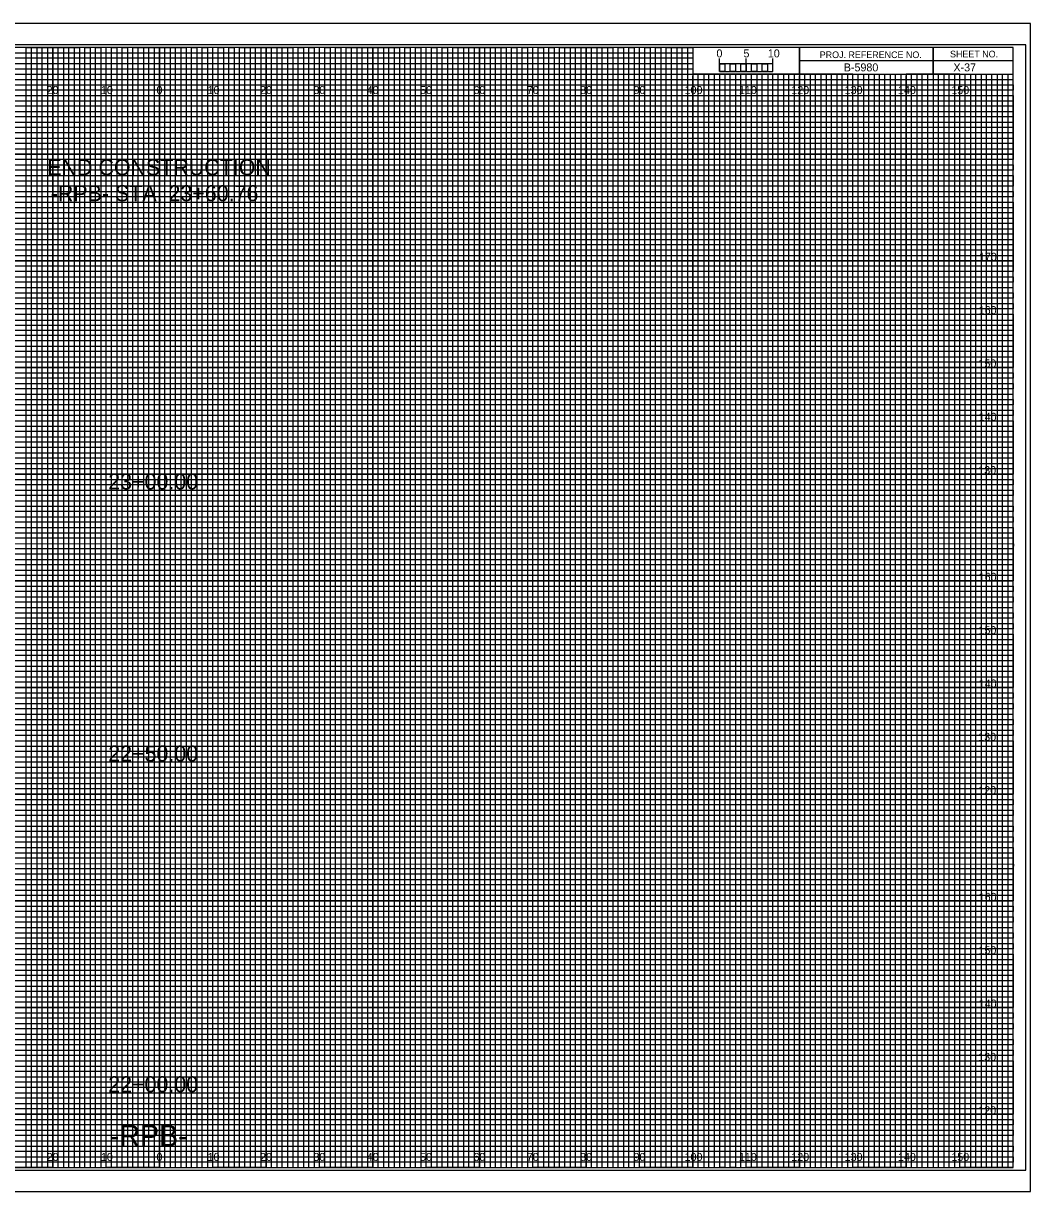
# Model space of a CAD drawing. Extents: x -13 to 323, y -5 to 1094.
# Drawn here: x 134.5 to 323.3, y 875.5 to 1094.5 of the extents above; entities that cross this region are included whole.
import ezdxf

# ---------------------------------------------------------------- set-up
doc = ezdxf.new("R2010")
doc.units = 0
for name, color, linetype in [('Exist Cross Section Cell', 7, 'Continuous'), ('Exist XS Center Line Elevation Label', 7, 'Continuous'), ('Exist XS Ground Line', 7, 'Continuous'), ('Prop CMT Concrete Structures', 7, 'Continuous'), ('Prop CMT Guardrail Graphics', 7, 'Continuous'), ('Prop CMT Pvmt Course 1', 7, 'Continuous'), ('Prop CMT Pvmt Course 1 CG', 7, 'Continuous'), ('Prop CMT Pvmt Course 2', 7, 'Continuous'), ('Prop CMT Pvmt Course 3', 7, 'Continuous'), ('Prop CMT Pvmt Surface', 7, 'Continuous'), ('Prop CMT Pvmt Surface Shoulder', 7, 'Continuous'), ('Prop CMT Shld Paved Course 1', 7, 'Continuous'), ('Prop CMT Shld Paved Course 2', 7, 'Continuous'), ('Prop CMT Shld Paved Course 3', 7, 'Continuous'), ('Prop CMT Slope Grass', 7, 'Continuous'), ('Prop CMT Subgrade Earthwork', 7, 'Continuous'), ('Scratch_Level_1', 7, 'Continuous')]:
    doc.layers.add(name, color=color, linetype=linetype)

msp = doc.modelspace()

# ---------------------------------------------------------------- linework, layer by layer
at = {"layer": 'Exist XS Center Line Elevation Label'}
for points in [[(125, 880), (135, 880), (135, 1090), (145, 1090), (145, 880), (155, 880), (155, 1090), (165, 1090), (165, 880), (175, 880), (175, 1090), (185, 1090), (185, 880), (195, 880), (195, 1090), (205, 1090), (205, 880), (215, 880), (215, 1090), (225, 1090), (225, 880), (235, 880), (235, 1090), (245, 1090), (245, 880), (255, 880), (255, 1090), (259.93, 1090), (260, 1090), (260, 1085), (264.99, 1085), (264.99, 880), (275, 880), (275, 1085), (285, 1085), (285, 880), (295, 880), (295, 1085), (305, 1085), (305, 880), (315, 880), (315, 1085)], [(0, 1085), (275, 1085)], [(0, 1065), (320, 1065), (320, 1075), (0, 1075)], [(0, 1045), (320, 1045), (320, 1055), (0, 1055)], [(0, 1025), (320, 1025), (320, 1035), (0, 1035)], [(0, 1005), (320, 1005), (320, 1015), (0, 1015)], [(0, 985), (320, 985), (320, 995), (0, 995)], [(0, 965), (320, 965), (320, 975), (0, 975)], [(0, 945), (320, 945), (320, 955), (0, 955)], [(0, 925), (320, 925), (320, 935), (0, 935)], [(0, 905), (320, 905), (320, 915), (0, 915)], [(0, 885), (320, 885), (320, 895), (0, 895)]]:
    msp.add_lwpolyline(points, dxfattribs=at)
at = {"layer": 'Exist XS Ground Line'}
for p, q in [((150, 1090), (140, 1090)), ((140, 1090), (140, 880)), ((150, 880), (150, 1090)), ((170, 1090), (160, 1090)), ((160, 1090), (160, 880)), ((170, 880), (170, 1090)), ((190, 1090), (180, 1090)), ((180, 1090), (180, 880)), ((190, 880), (190, 1090)), ((210, 1090), (200, 1090)), ((200, 1090), (200, 880)), ((210, 880), (210, 1090)), ((230, 1090), (220, 1090)), ((220, 1090), (220, 880)), ((230, 880), (230, 1090)), ((250, 1090), (240, 1090)), ((240, 1090), (240, 880)), ((250, 880), (250, 1090)), ((260, 1090), (260, 880)), ((270, 880), (270, 1085)), ((290, 1085), (280, 1085)), ((280, 1085), (280, 880)), ((290, 880), (290, 1085)), ((310, 1085), (300, 1085)), ((300, 1085), (300, 880)), ((310, 880), (310, 1085)), ((140, 880), (130, 880)), ((160, 880), (150, 880)), ((180, 880), (170, 880)), ((200, 880), (190, 880)), ((220, 880), (210, 880)), ((240, 880), (230, 880)), ((260, 880), (250, 880)), ((280, 880), (270, 880)), ((300, 880), (290, 880)), ((320, 880), (310, 880)), ((320, 880), (320, 880))]:
    msp.add_line(p, q, dxfattribs=at)
for points in [[(0, 1080), (320, 1080), (320, 1070), (0, 1070)], [(0, 1060), (320, 1060), (320, 1050), (0, 1050)], [(0, 1040), (320, 1040), (320, 1030), (0, 1030)], [(0, 1020), (320, 1020), (320, 1010), (0, 1010)], [(0, 1000), (320, 1000), (320, 990), (0, 990)], [(0, 980), (320, 980), (320, 970), (0, 970)], [(0, 960), (320, 960), (320, 950), (0, 950)], [(0, 940), (320, 940), (320, 930), (0, 930)], [(0, 920), (320, 920), (320, 910), (0, 910)], [(0, 900), (320, 900), (320, 890), (0, 890)]]:
    msp.add_lwpolyline(points, dxfattribs=at)
at = {"layer": 'Prop CMT Pvmt Course 2'}
for p, q in [((265, 1085.49), (265, 1087.9)), ((265, 1086.9), (265, 1087.9)), ((270, 1085.49), (270, 1087.9)), ((275, 1085.49), (275, 1087.9)), ((275, 1086.9), (275, 1087.9))]:
    msp.add_line(p, q, dxfattribs=at)
for points in [[(275, 1086.9), (265, 1086.9), (265, 1085.49), (275, 1085.49)], [(265, 1086.9), (266, 1086.9), (266, 1085.49), (265, 1085.49)], [(267, 1086.9), (268, 1086.9), (268, 1085.49), (267, 1085.49)], [(269, 1086.9), (270, 1086.9), (270, 1085.49), (269, 1085.49)], [(271, 1086.9), (272, 1086.9), (272, 1085.49), (271, 1085.49)], [(273, 1086.9), (274, 1086.9), (274, 1085.49), (273, 1085.49)]]:
    msp.add_lwpolyline(points, close=True, dxfattribs=at)
at = {"layer": 'Prop CMT Pvmt Course 3'}
msp.add_lwpolyline([(-13.4, 875.5), (323.3, 875.5), (323.3, 1094.5), (-13.4, 1094.5)], close=True, dxfattribs=at)
at = {"layer": 'Prop CMT Pvmt Surface'}
for p, q in [((140, 880), (140, 1090)), ((150, 880), (150, 1090)), ((160, 880), (160, 1090)), ((170, 880), (170, 1090)), ((180, 880), (180, 1090)), ((190, 880), (190, 1090)), ((200, 880), (200, 1090)), ((210, 880), (210, 1090)), ((220, 880), (220, 1090)), ((230, 880), (230, 1090)), ((240, 880), (240, 1090)), ((250, 880), (250, 1090)), ((260, 880), (260, 1084.69)), ((270, 880), (270, 1084.69)), ((280, 880), (280, 1084.69)), ((290, 880), (290, 1084.69)), ((300, 880), (300, 1084.69)), ((310, 880), (310, 1084.69)), ((0, 1080), (320, 1080)), ((0, 1070), (320, 1070)), ((0, 1060), (320, 1060)), ((0, 1050), (320, 1050)), ((0, 1040), (320, 1040)), ((0, 1030), (320, 1030)), ((0, 1020), (320, 1020)), ((0, 1010), (320, 1010)), ((0, 1000), (320, 1000)), ((0, 990), (320, 990)), ((0, 980), (320, 980)), ((0, 970), (320, 970)), ((0, 960), (320, 960)), ((0, 950), (320, 950)), ((0, 940), (320, 940)), ((0, 930), (320, 930)), ((0, 920), (320, 920)), ((0, 910), (320, 910)), ((0, 900), (320, 900)), ((0, 890), (320, 890))]:
    msp.add_line(p, q, dxfattribs=at)
at = {"layer": 'Prop CMT Pvmt Surface Shoulder'}
for p, q in [((323.3, 1094.5), (-13.4, 1094.5)), ((-13.4, 875.5), (323.3, 875.5))]:
    msp.add_line(p, q, dxfattribs=at)
at = {"layer": 'Prop CMT Shld Paved Course 1'}
for p, q in [((0, 1089), (260, 1089)), ((260, 1089), (260, 1087.98)), ((260, 1087.98), (0, 1087.98)), ((0, 1087), (260, 1087)), ((260, 1087), (260, 1085.89)), ((260, 1085.89), (0, 1085.89)), ((0, 1084), (320, 1084))]:
    msp.add_line(p, q, dxfattribs=at)
for points in [[(0, 1083), (270, 1083), (320, 1083), (320, 1082), (0, 1082)], [(0, 1081), (320, 1081), (320, 1079), (0, 1079)], [(0, 1078), (320, 1078), (320, 1077), (0, 1076.98)], [(0, 1076), (320, 1076), (320, 1074), (0, 1074)], [(0, 1073), (320, 1073), (320, 1072), (0, 1072)], [(0, 1071), (320, 1071), (320, 1069), (0, 1069)], [(0, 1068), (320, 1068), (320, 1067), (0, 1067)], [(0, 1066), (320, 1066), (320, 1064), (0, 1064)], [(0, 1063), (320, 1063), (320, 1062), (0, 1062)], [(0, 1061), (320, 1061), (320, 1059), (0, 1059)], [(0, 1058), (320, 1058), (320, 1057), (0, 1057)], [(0, 1056), (320, 1056), (320, 1053.95), (320, 1053), (320, 1052), (0, 1052)], [(0, 1054), (320, 1054), (320, 1053), (0, 1053)], [(0, 1051), (320, 1051), (320, 1049), (0, 1049.03)], [(0, 1049.03), (320, 1049), (320, 1048), (0, 1048)], [(0, 1047), (320, 1047), (320, 1046), (0, 1046)], [(0, 1044), (320, 1044), (320, 1043), (0, 1043)], [(0, 1042), (320, 1042), (320, 1041), (0, 1041)], [(-0.07, 1038.89), (320, 1038.89), (320, 1037.88), (-0.07, 1037.88)], [(0, 1037), (320, 1037), (320, 1036), (0, 1036)], [(0, 1034), (320, 1034), (320, 1033), (0, 1033)], [(0, 1032), (320, 1032), (320, 1031), (0, 1031)], [(0, 1029), (320, 1029), (320, 1028), (0, 1028)], [(0, 1027), (320, 1027), (320, 1026), (0, 1026)], [(0, 1024), (320, 1024), (320, 1023), (0, 1023)], [(0, 1022), (320, 1022), (320, 1021), (0, 1021)], [(0, 1019), (320, 1019), (319.99, 1017.98), (0, 1018)], [(0, 1017), (320, 1017), (320, 1016), (0, 1016)], [(0, 1014), (320, 1014), (320, 1013), (0, 1013)], [(0, 1012), (320, 1012), (320, 1011), (0, 1011)], [(0, 1009), (320, 1009), (320, 1008), (0, 1008)], [(0, 1007), (320, 1007), (320, 1006), (0, 1006)], [(0, 1004), (320, 1004), (320, 1003), (0, 1003)], [(0, 1002), (320, 1002), (320, 1001), (0, 1001)], [(0, 999), (320, 999), (320, 998), (0, 998)], [(0, 996.99), (320.07, 996.91), (320, 996), (0, 996)], [(0, 994), (320, 994), (320, 993), (0, 993)], [(0, 992), (320, 992), (320, 991), (0, 991)], [(0, 989), (320, 989), (320, 988), (0, 988)], [(0, 987), (320, 987), (320, 986), (0, 986)], [(0, 984), (320, 984), (320, 983), (0, 983)], [(0, 982), (320, 982), (320, 981), (0, 981)], [(0, 979), (320, 979), (320, 978), (0, 978)], [(0, 977), (320, 977), (320, 976), (0, 976)], [(0, 974), (320, 974), (320, 973), (0, 973)], [(0, 972), (320, 972), (320, 971), (0, 971)], [(0, 969), (320, 969), (320, 968), (0, 968)], [(0, 967), (320, 967), (320, 966), (0, 966)], [(0, 964), (320, 964), (320, 963), (0, 963)], [(0, 962), (320, 962), (320, 961), (0, 961)], [(0, 959), (320, 959), (319.99, 957.98), (0, 958)], [(0, 957), (320, 957), (320, 956), (0, 956)], [(0, 954), (320, 954), (320, 953), (0, 953)], [(0, 952), (320, 952), (320, 951), (0, 951)], [(0, 949), (320, 949), (320, 948), (0, 948)], [(0, 947), (320, 947), (320, 946), (0, 946)], [(0, 944), (320, 944), (320, 943), (0, 943)], [(0, 942), (320, 942), (320, 941), (0, 941)], [(0, 939), (320, 939), (320, 938), (0, 938)], [(0, 936.99), (320.07, 936.91), (320, 936), (0, 936)], [(0, 934), (320, 934), (320, 933), (0, 933)], [(0, 932), (320, 932), (320, 931), (0, 931)], [(0, 929), (320, 929), (320, 928), (0, 928)], [(0, 927), (320, 927), (320, 926), (0, 926)], [(0, 924), (320, 924), (320, 923), (0, 923)], [(0, 922), (320, 922), (320, 921), (0, 921)], [(0, 919), (320, 919), (320, 918), (0, 918)], [(0, 917), (320, 917), (320, 916), (0, 916)], [(0, 914), (320, 914), (320, 913), (0, 913)], [(0, 912), (320, 912), (320, 911), (0, 911)], [(0, 909), (320, 909), (320, 908), (0, 908)], [(0, 907), (320, 907), (320, 906), (0, 906)], [(0, 904), (320, 904), (320, 903), (0, 903)], [(0, 902), (320, 902), (320, 901), (0, 901)], [(0, 899), (320, 899), (320, 898), (0, 898)], [(0, 897), (320, 897), (320, 896), (0, 896)], [(0, 894), (320, 894), (320, 893), (0, 893)], [(0, 892), (320, 892), (320, 891), (0, 891)], [(0, 889), (320, 889), (320, 888), (0, 888)], [(0, 887), (320, 887), (320, 886), (0, 886)], [(0, 884), (320, 884), (320, 883), (0, 883)], [(0, 882), (320, 882), (320, 881), (0, 881)]]:
    msp.add_lwpolyline(points, dxfattribs=at)
at = {"layer": 'Prop CMT Shld Paved Course 2'}
for p, q in [((305, 1090), (305, 1085)), ((305, 1085), (305, 1090)), ((280, 1087.5), (280, 1085)), ((320, 1087.49), (280, 1087.49)), ((280, 1085), (320, 1085))]:
    msp.add_line(p, q, dxfattribs=at)
for points in [[(320, 1090), (0, 1090), (0, 880), (320, 880)], [(280, 1090), (260, 1090), (260, 1085.03), (280, 1085.03)], [(320, 1090), (280, 1090), (280, 1085), (320, 1085)]]:
    msp.add_lwpolyline(points, close=True, dxfattribs=at)
at = {"layer": 'Prop CMT Shld Paved Course 3'}
for p, q in [((267, 1085), (266.01, 1085)), ((266.01, 1085), (266.01, 880)), ((267, 880), (267, 1085)), ((269, 1085), (268, 1085)), ((268, 1085), (268, 880)), ((269, 880), (269, 1085)), ((266.01, 880), (265, 880)), ((268, 880), (267, 880))]:
    msp.add_line(p, q, dxfattribs=at)
for points in [[(135, 880), (136, 880), (136, 1090), (137, 1090), (137, 880)], [(137, 880), (138, 880), (138, 1090), (139, 1090), (139, 880)], [(140, 880), (141, 880), (141, 1090), (142, 1090), (142, 880)], [(142, 880), (143, 880), (143, 1090), (144, 1090), (144, 880)], [(145, 880), (146, 880), (146, 1090), (147, 1090), (147, 880)], [(147, 880), (148, 880), (148, 1090), (149, 1090), (149, 880)], [(150, 880), (151, 880), (151, 1090), (152, 1090), (152, 880)], [(152, 880), (153, 880), (153, 1090), (154, 1090), (154, 880)], [(155, 880), (156, 880), (156, 1090), (157, 1090), (157, 880)], [(157, 880), (158, 880), (158, 1090), (159, 1090), (159, 880)], [(160, 880), (161, 880), (161, 1090), (162, 1090), (162, 880)], [(162, 880), (163, 880), (163, 1090), (164, 1090), (164, 880)], [(165, 880), (166, 880), (166, 1090), (167, 1090), (167, 880)], [(167, 880), (168, 880), (168, 1090), (169, 1090), (169, 880)], [(170, 880), (171, 880), (171, 1090), (172, 1090), (172, 880)], [(172, 880), (173, 880), (173, 1090), (174, 1090), (174, 880)], [(175, 880), (176, 880), (176, 1090), (177, 1090), (177, 880)], [(177, 880), (178, 880), (178, 1090), (179, 1090), (179, 880)], [(180, 880), (181, 880), (181, 1090), (182, 1090), (182, 880)], [(182, 880), (183, 880), (183, 1090), (184, 1090), (184, 880)], [(185, 880), (186, 880), (186, 1090), (187, 1090), (187, 880)], [(187, 880), (188, 880), (188, 1090), (189, 1090), (189, 880)], [(190, 880), (191, 880), (191, 1090), (192, 1090), (192, 880)], [(192, 880), (193, 880), (193, 1090), (194, 1090), (194, 880)], [(195, 880), (196, 880), (196, 1090), (197, 1090), (197, 880)], [(197, 880), (198, 880), (198, 1090), (199, 1090), (199, 880)], [(200, 880), (201, 880), (201, 1090), (202, 1090), (202, 880)], [(202, 880), (203, 880), (203, 1090), (204, 1090), (204, 880)], [(205, 880), (206, 880), (206, 1090), (207, 1090), (207, 880)], [(207, 880), (208, 880), (208, 1090), (209, 1090), (209, 880)], [(210, 880), (211, 880), (211, 1090), (212, 1090), (212, 880)], [(212, 880), (213, 880), (213, 1090), (214, 1090), (214, 880)], [(215, 880), (216, 880), (216, 1090), (217, 1090), (217, 880)], [(217, 880), (218, 880), (218, 1090), (219, 1090), (219, 880)], [(220, 880), (221, 880), (221, 1090), (222, 1090), (222, 880)], [(222, 880), (223, 880), (223, 1090), (224, 1090), (224, 880)], [(225, 880), (226, 880), (226, 1090), (227, 1090), (227, 880)], [(227, 880), (228, 880), (228, 1090), (229, 1090), (229, 880)], [(230, 880), (231, 880), (231, 1090), (232, 1090), (232, 880)], [(232, 880), (233, 880), (233, 1090), (234, 1090), (234, 880)], [(235, 880), (236, 880), (236, 1090), (237, 1090), (237, 880)], [(237, 880), (238, 880), (238, 1090), (239, 1090), (239, 880)], [(240, 880), (241, 880), (241, 1090), (242, 1090), (242, 880)], [(242, 880), (243, 880), (243, 1090), (244, 1090), (244, 880)], [(245, 880), (246, 880), (246, 1090), (247, 1090), (247, 880)], [(247, 880), (248, 880), (248, 1090), (249, 1090), (249, 880)], [(250, 880), (251, 880), (251, 1090), (252, 1090), (252, 880)], [(252, 880), (253, 880), (253, 1090), (254, 1090), (254, 880)], [(255, 880), (256, 880), (256, 1090), (257, 1090), (257, 880)], [(257, 880), (258, 880), (258, 1090), (259, 1090), (259, 880)], [(260, 880), (261, 880), (261, 1085), (262.02, 1085), (262.02, 880)], [(262, 880), (263, 880), (263, 1085), (263.99, 1085), (263.99, 880)], [(270, 880), (270.98, 880), (270.98, 1085), (272, 1085), (272, 880)], [(272, 880), (273, 880), (273, 1085), (274.05, 1085), (274.05, 880)], [(275, 880), (276, 880), (276, 1085), (277, 1085), (277, 880)], [(277, 880), (278, 880), (278, 1085), (279, 1085), (279, 880)], [(280, 880), (281, 880), (281, 1085), (282, 1085), (282, 880)], [(282, 880), (283, 880), (283, 1085), (284, 1085), (284, 880)], [(285, 880), (286, 880), (286, 1085), (287, 1085), (287, 880)], [(287, 880), (288, 880), (288, 1085), (289, 1085), (289, 880)], [(290, 880), (291, 880), (291, 1085), (292, 1085), (292, 880)], [(292, 880), (293, 880), (293, 1085), (294, 1085), (294, 880)], [(295, 880), (296, 880), (296, 1085), (297, 1085), (297, 880)], [(297, 880), (298, 880), (298, 1085), (299, 1085), (299, 880)], [(300, 880), (301, 880), (301, 1085), (302, 1085), (302, 880)], [(302, 880), (303, 880), (303, 1085), (304, 1085), (304, 880)], [(305, 880), (306, 880), (306, 1085), (307, 1085), (307, 880)], [(307, 880), (308, 880), (308, 1085), (309, 1085), (309, 880)], [(310, 880), (311, 880), (311, 1085), (312, 1085), (312, 880)], [(312, 880), (313, 880), (313, 1085), (314, 1085), (314, 880)], [(315, 880), (316, 880), (316, 1085), (317, 1085), (317, 880)], [(317, 880), (318, 880), (318, 1085), (319, 1085), (319, 880)]]:
    msp.add_lwpolyline(points, dxfattribs=at)
at = {"layer": 'Prop CMT Subgrade Earthwork'}
msp.add_lwpolyline([(-10.8, 879.5), (322.4, 879.5), (322.4, 1090.5), (-10.8, 1090.5)], close=True, dxfattribs=at)

# ---------------------------------------------------------------- texts
at = {"layer": 'Exist Cross Section Cell'}
for s, p in [('20', (138.86, 1081.25)), ('10', (149.04, 1081.25)), ('0', (159.45, 1081.25)), ('0', (159.45, 1081.25)), ('10', (169.04, 1081.25)), ('20', (178.86, 1081.25)), ('30', (188.86, 1081.25)), ('40', (198.86, 1081.25)), ('50', (208.86, 1081.25)), ('60', (218.86, 1081.25)), ('70', (228.86, 1081.25)), ('80', (238.86, 1081.25)), ('90', (248.86, 1081.25)), ('100', (258.44, 1081.25)), ('110', (268.62, 1081.25)), ('120', (278.44, 1081.25)), ('130', (288.44, 1081.25)), ('140', (298.44, 1081.25)), ('150', (308.44, 1081.25)), ('20', (138.86, 881.25)), ('10', (149.04, 881.25)), ('0', (159.45, 881.25)), ('0', (159.45, 881.25)), ('10', (169.04, 881.25)), ('20', (178.86, 881.25)), ('30', (188.86, 881.25)), ('40', (198.86, 881.25)), ('50', (208.86, 881.25)), ('60', (218.86, 881.25)), ('70', (228.86, 881.25)), ('80', (238.86, 881.25)), ('90', (248.86, 881.25)), ('100', (258.44, 881.25)), ('110', (268.62, 881.25)), ('120', (278.44, 881.25)), ('130', (288.44, 881.25)), ('140', (298.44, 881.25)), ('150', (308.44, 881.25))]:
    msp.add_text(s, height=1.5, dxfattribs=at).set_placement(p)
at = {"layer": 'Prop CMT Concrete Structures'}
msp.add_text('-RPB-', height=4, dxfattribs=at).set_placement((150.72, 884))
at = {"layer": 'Prop CMT Guardrail Graphics'}
msp.add_text('X-37', height=1.5, dxfattribs=at).set_placement((308.83, 1085.5))
at = {"layer": 'Prop CMT Pvmt Course 1'}
for s, p in [('170', (313.61, 1050)), ('160', (313.57, 1040)), ('150', (313.52, 1030)), ('140', (313.57, 1020)), ('130', (313.49, 1010)), ('160', (313.57, 990)), ('150', (313.52, 980)), ('140', (313.57, 970)), ('130', (313.49, 960)), ('120', (313.5, 950)), ('160', (313.57, 930)), ('150', (313.52, 920)), ('140', (313.57, 910)), ('130', (313.49, 900)), ('120', (313.5, 890))]:
    msp.add_text(s, height=1.5, dxfattribs=at).set_placement(p)
at = {"layer": 'Prop CMT Pvmt Course 1 CG'}
for s, p in [('5', (269.47, 1088.12)), ('10', (274.04, 1088.12))]:
    msp.add_text(s, height=1.5, dxfattribs=at).set_placement(p)
at = {"layer": 'Prop CMT Pvmt Course 2'}
msp.add_text('0', height=1.5, dxfattribs=at).set_placement((264.41, 1088.12))
at = {"layer": 'Prop CMT Shld Paved Course 2'}
for s, p in [('PROJ. REFERENCE NO.', (283.77, 1087.99)), ('SHEET NO.', (308.19, 1088.12))]:
    msp.add_text(s, height=1.25, dxfattribs=at).set_placement(p)
at = {"layer": 'Prop CMT Slope Grass'}
for s, p in [('END CONSTRUCTION', (138.99, 1066.03)), ('-RPB- STA. 23+60.76', (139.64, 1061.16)), ('23+00.00', (150.41, 1007.13)), ('22+50.00', (150.41, 956.13)), ('22+00.00', (150.41, 894.13))]:
    msp.add_text(s, height=3, dxfattribs=at).set_placement(p)
at = {"layer": 'Scratch_Level_1'}
msp.add_text('B-5980', height=1.5, dxfattribs=at).set_placement((288.28, 1085.5))

doc.saveas('drawing.dxf')
